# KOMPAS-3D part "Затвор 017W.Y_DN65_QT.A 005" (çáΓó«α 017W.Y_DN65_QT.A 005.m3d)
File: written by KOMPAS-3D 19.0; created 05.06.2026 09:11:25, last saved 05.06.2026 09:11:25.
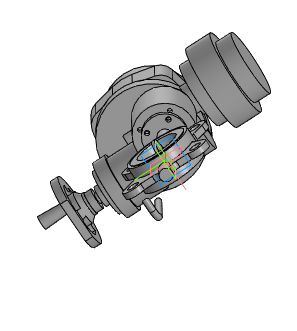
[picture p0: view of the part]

Document properties: Автор: Энергия; Полное имя файла: ..\..\..\3d для проектировщиков\x.x Тип 017W.Y(S) Затвор дисковый поворотный межфланцевый\Затвор 017W.Y(S)_DN32-DN1200_QT.A_MT903.A\Затвор 017W.Y_DN65_QT.A 005.a3d

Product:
- Part/product: Затвор 017W.Y_DN65_QT.A 005
    Масса: 38.6072

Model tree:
1. Операция без истории:1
